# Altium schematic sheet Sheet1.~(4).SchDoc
size A4; SheetNumber: 1; SheetTotal: 1
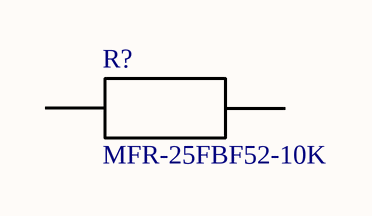
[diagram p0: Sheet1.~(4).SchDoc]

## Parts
R?  MFR-25FBF52-10K  [RESAD1100W55L680D260]

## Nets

Not connected (* = marked no-connect by the designer): R? 1 2

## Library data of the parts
R? = MFR-25FBF52-10K: 10.2 kOhms Â±1% 0.25W, 1/4W Through Hole Resistor Axial - Metal Film; MF: Yageo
